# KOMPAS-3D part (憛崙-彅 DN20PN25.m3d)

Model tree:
1. Объединить компоненты:1  (labels: СЕНС-ПФ DN20PN25)

Referenced files in D:\Савин\!СЕНСОР\3D для заказчика\!Новый перечень\СЕНС-ПФ\DN20\: СЕНС-ПФ DN20PN25.a3d
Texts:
  СЕНС-ПФ DN20PN25
  ООО НПП Сенсор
